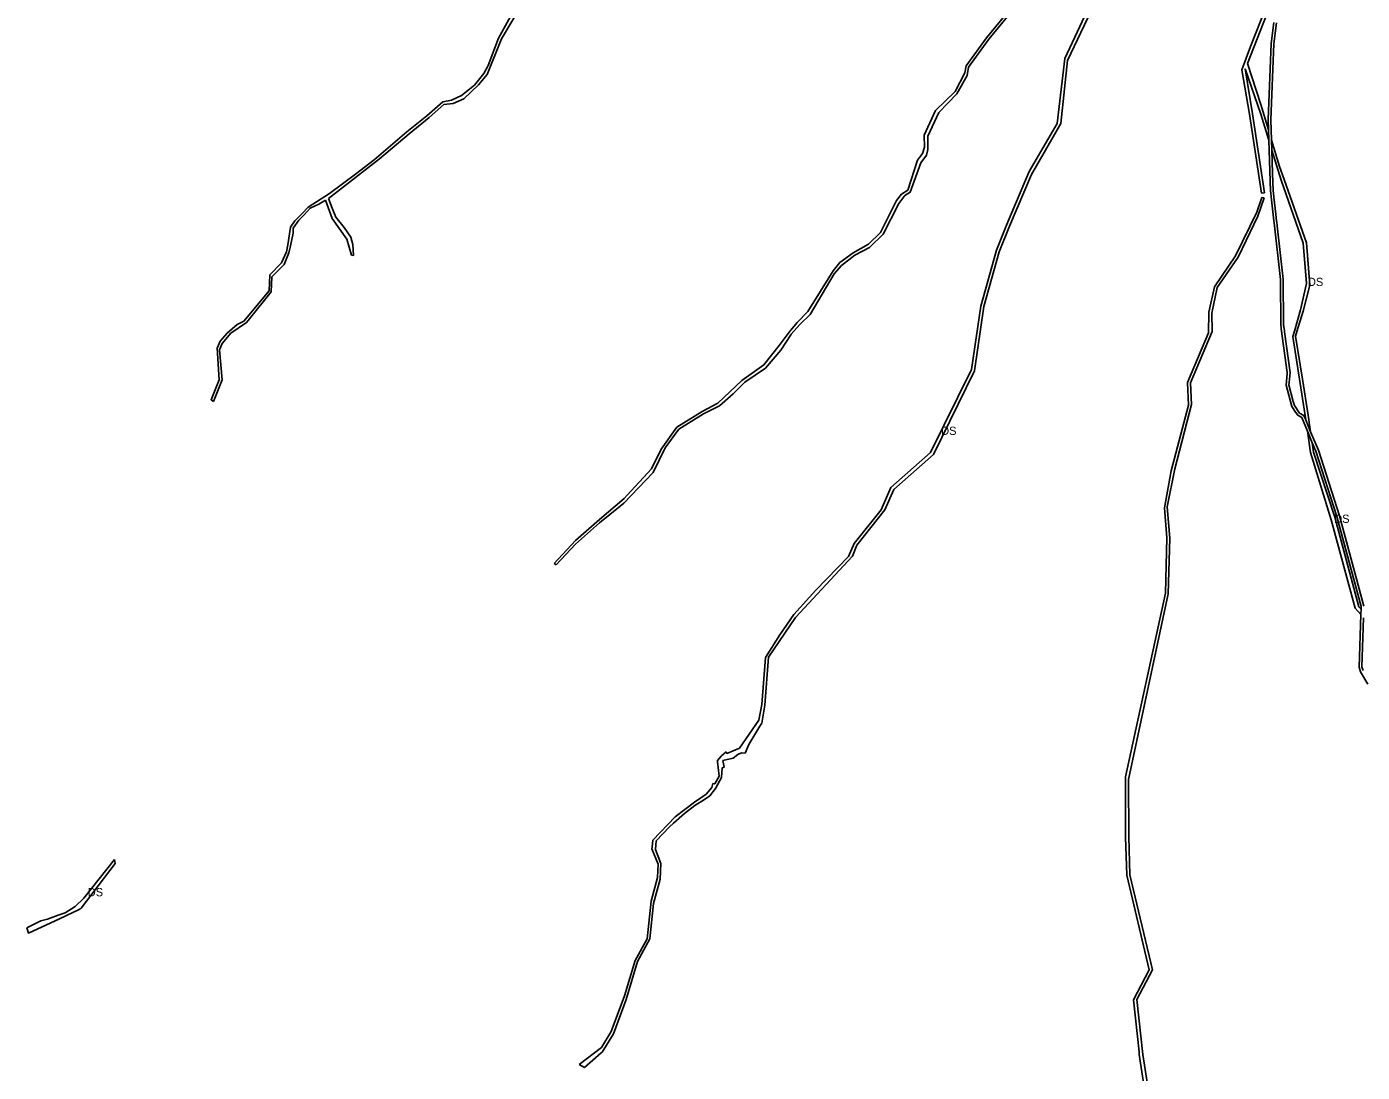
# Model space of a CAD drawing. Extents: x -477304 to -465641, y -1159113 to -1149285.
# Drawn here: x -475398 to -473942, y -1157333 to -1156193 of the extents above; entities that cross this region are included whole.
import ezdxf

# ---------------------------------------------------------------- set-up
doc = ezdxf.new("R2010")
doc.units = 0
doc.layers.add('35', color=7, linetype='Continuous')
doc.layers.add('4', color=7, linetype='Continuous')

msp = doc.modelspace()

# ---------------------------------------------------------------- linework, layer by layer
at = {"layer": '35'}
for p, q in [((-474263.1, -1156230.3), (-474209.5, -1156117.1)), ((-474861.1, -1156165.1), (-474883.8, -1156206)), ((-474045.7, -1156169.9), (-474063.4, -1156215)), ((-474883.8, -1156206), (-474894.9, -1156235.6)), ((-474052.4, -1156278.4), (-474066.8, -1156233.6)), ((-474069.5, -1156239.5), (-474052.4, -1156288.7)), ((-474933.1, -1156277.3), (-474921.4, -1156271.9)), ((-474961.9, -1156290.5), (-474983.6, -1156308.2)), ((-474044, -1156306), (-474052.4, -1156278.4)), ((-474052.4, -1156288.7), (-474043.6, -1156317.1)), ((-474043.6, -1156317.1), (-474044, -1156306)), ((-474983.6, -1156308.2), (-475019.2, -1156338.6)), ((-475013.4, -1156337.4), (-474981.2, -1156310.1)), ((-474419.6, -1156311.6), (-474419.2, -1156324.6)), ((-474031.9, -1156345.9), (-474040.6, -1156317.2)), ((-474040.6, -1156317.2), (-474040.2, -1156327.9)), ((-474040.2, -1156327.9), (-474030.1, -1156360.6)), ((-475069.1, -1156380.7), (-475013.4, -1156337.4)), ((-475019.2, -1156338.6), (-475039.6, -1156354.1)), ((-474026.8, -1156359.9), (-474031.9, -1156345.9)), ((-475039.6, -1156354.1), (-475068.2, -1156375.1)), ((-474305, -1156351.4), (-474329.7, -1156409.8)), ((-474326.2, -1156411), (-474302.2, -1156354.4)), ((-475068.2, -1156375.1), (-475091.4, -1156390.2)), ((-474051.6, -1156374.9), (-474048.3, -1156374.7)), ((-474048.7, -1156380), (-474051.2, -1156379.6)), ((-475079.7, -1156386.7), (-475072.4, -1156382.6)), ((-475072.4, -1156382.6), (-475065.2, -1156402.4)), ((-475065.1, -1156391.3), (-475069.1, -1156380.7)), ((-475061.2, -1156401), (-475065.1, -1156391.3)), ((-475105.9, -1156405.1), (-475110.5, -1156411.9)), ((-475052.1, -1156412.4), (-475061.2, -1156401)), ((-474329.7, -1156409.8), (-474340.5, -1156437.1)), ((-475041.8, -1156442.8), (-475042.4, -1156431)), ((-474495.1, -1156442.4), (-474479.2, -1156434.1)), ((-474340.5, -1156437.1), (-474357.5, -1156498.2)), ((-475131.1, -1156466.2), (-475117.6, -1156452.6)), ((-475044, -1156442.4), (-475041.8, -1156442.8)), ((-474496.7, -1156439.8), (-474511.4, -1156450.4)), ((-474079.8, -1156443.2), (-474102.7, -1156476.8)), ((-474099.7, -1156477.6), (-474077, -1156444.5)), ((-475133, -1156463.8), (-475134, -1156481.5)), ((-475131.5, -1156482.5), (-475131.1, -1156466.2)), ((-474543.6, -1156507.3), (-474517.5, -1156462.8)), ((-474105.8, -1156505.7), (-474099.7, -1156477.6)), ((-475155.1, -1156511.8), (-475131.5, -1156482.5)), ((-474554.9, -1156518.1), (-474543.6, -1156507.3)), ((-474012.9, -1156525.6), (-474006.2, -1156503.4)), ((-475158.5, -1156516), (-475155.1, -1156511.8)), ((-474565.6, -1156525), (-474577.7, -1156541)), ((-474014.3, -1156530.6), (-474012.9, -1156525.6)), ((-475190.6, -1156543.9), (-475188.5, -1156578.4)), ((-474592.6, -1156565.6), (-474575.7, -1156546)), ((-474409.3, -1156659.8), (-474364.4, -1156568.6)), ((-474003.3, -1156621.9), (-473997.9, -1156635)), ((-474689.1, -1156630.1), (-474706.4, -1156654.1)), ((-473996.1, -1156647), (-474001.4, -1156634.3)), ((-474001.4, -1156634.3), (-473997.9, -1156657.7)), ((-474706.4, -1156654.1), (-474716.9, -1156675.5)), ((-474714.9, -1156679.2), (-474701.9, -1156652.6)), ((-474452.4, -1156697.8), (-474409.3, -1156659.8)), ((-474799.8, -1156757.5), (-474773.7, -1156734.3)), ((-474820.7, -1156780.1), (-474799.8, -1156757.5)), ((-474822.9, -1156778.7), (-474820.7, -1156780.1)), ((-473942.9, -1156828.4), (-473945.3, -1156825.6)), ((-473943.1, -1156834.3), (-473942.9, -1156828.4)), ((-474596.6, -1156932.1), (-474599.7, -1156949.2)), ((-474596.5, -1156952.5), (-474593.1, -1156932.8)), ((-474610.7, -1156976), (-474598.6, -1156955.9)), ((-474598.6, -1156955.9), (-474596.5, -1156952.5)), ((-474614.7, -1156985.2), (-474610.7, -1156976)), ((-474639.2, -1156993.1), (-474627.9, -1156990.7)), ((-474627.9, -1156990.7), (-474622.6, -1156986.8)), ((-474622.6, -1156986.8), (-474618.7, -1156985)), ((-474618.7, -1156985), (-474614.7, -1156985.2)), ((-474644.7, -1156994.7), (-474644.2, -1157000.9)), ((-474644.2, -1157000.9), (-474642.9, -1157010.4)), ((-474640.6, -1157011.8), (-474639.9, -1157001.2)), ((-474639.9, -1157001.2), (-474637.5, -1157000.7)), ((-474637.5, -1157000.7), (-474639.2, -1156993.1)), ((-474650, -1157018.2), (-474651, -1157022.6)), ((-474647.1, -1157023.7), (-474640.6, -1157011.8)), ((-474660.9, -1157032.5), (-474670, -1157038.6)), ((-474669.4, -1157042.2), (-474659.2, -1157035.6)), ((-474657.3, -1157030.1), (-474660.9, -1157032.5)), ((-474659.2, -1157035.6), (-474653.1, -1157031.7)), ((-474651, -1157022.6), (-474657.3, -1157030.1)), ((-474653.1, -1157031.7), (-474647.1, -1157023.7)), ((-474716.1, -1157087.7), (-474716.3, -1157089.4)), ((-474712.3, -1157090.1), (-474711.8, -1157081)), ((-474706.6, -1157105.5), (-474712.3, -1157090.1)), ((-475339, -1157154.1), (-475301.8, -1157105.4)), ((-475301.8, -1157105.4), (-475302.4, -1157101.1)), ((-474718.6, -1157187.5), (-474714.6, -1157149.1)), ((-475341.1, -1157155.7), (-475339, -1157154.1)), ((-475382.7, -1157168.2), (-475398.3, -1157175.8)), ((-474732, -1157212.5), (-474718.6, -1157187.5)), ((-474187.4, -1157253.9), (-474170.3, -1157221.5)), ((-474181.1, -1157313.9), (-474187.4, -1157253.9)), ((-474790, -1157328), (-474771.6, -1157312)), ((-474771.6, -1157312), (-474770.6, -1157311.1)), ((-474185.1, -1157310.8), (-474184.8, -1157313.7)), ((-474795.9, -1157324.7), (-474790, -1157328)), ((-474184.8, -1157313.7), (-474179.7, -1157346.8)), ((-474175.7, -1157346.4), (-474181.1, -1157313.9))]:
    msp.add_line(p, q, dxfattribs=at)
for points in [[(-474204.1, -1156055.4), (-474206.1, -1156090.1), (-474206.5, -1156100.7), (-474266.2, -1156228.1)], [(-474372.4, -1156246.7), (-474371, -1156237.6), (-474349, -1156207.2), (-474328.4, -1156182.4), (-474319.5, -1156169.6), (-474292.1, -1156141.7), (-474279.6, -1156131)], [(-474066.8, -1156233.6), (-474042.5, -1156171.3), (-474049, -1156144.7)], [(-474921.4, -1156271.9), (-474905.6, -1156256.9), (-474896.2, -1156245.6), (-474880.6, -1156206.5), (-474861, -1156174.5)], [(-474331.2, -1156180.9), (-474351.5, -1156205.7), (-474373.5, -1156236.1)], [(-474063.4, -1156215), (-474073.1, -1156240.3), (-474064.5, -1156288.7), (-474051.6, -1156374.9)], [(-474266.2, -1156228.1), (-474274.3, -1156298.9), (-474305, -1156351.4)], [(-474302.2, -1156354.4), (-474270.3, -1156299.1), (-474263.1, -1156230.3)], [(-474894.9, -1156235.6), (-474899.6, -1156244.5), (-474909.7, -1156257)], [(-474373.5, -1156236.1), (-474375.2, -1156243.9), (-474385.7, -1156264.1), (-474407, -1156284.7), (-474419.6, -1156311.6)], [(-474403.5, -1156287.1), (-474383.8, -1156266.6), (-474372.4, -1156246.7)], [(-474048.3, -1156374.7), (-474061.3, -1156288.5), (-474069.5, -1156239.5)], [(-474909.7, -1156257), (-474923.9, -1156268.3), (-474935, -1156273.4)], [(-474981.2, -1156310.1), (-474959.5, -1156292.5), (-474943.3, -1156278.2), (-474933.1, -1156277.3)], [(-474935, -1156273.4), (-474944.5, -1156275.5), (-474961.9, -1156290.5)], [(-474415.5, -1156327.2), (-474415.5, -1156312.9), (-474403.5, -1156287.1)], [(-474447.2, -1156386.1), (-474440.4, -1156377.6), (-474434.7, -1156373.8), (-474423, -1156341.8), (-474416.8, -1156333.3), (-474415.5, -1156327.2)], [(-474419.2, -1156324.6), (-474421.3, -1156331.6), (-474426.7, -1156338.9), (-474437.3, -1156371.7)], [(-474030.1, -1156360.6), (-474006, -1156429.4), (-474002.3, -1156473.4), (-474008.9, -1156502), (-474015.5, -1156525.3)], [(-474006.2, -1156503.4), (-473998.8, -1156475.1), (-474002.6, -1156429), (-474026.8, -1156359.9)], [(-474437.3, -1156371.7), (-474444, -1156375.8), (-474449.6, -1156382.7), (-474467, -1156417.6)], [(-474051.2, -1156379.6), (-474056.6, -1156395.7), (-474079.8, -1156443.2)], [(-474077, -1156444.5), (-474055.5, -1156399.9), (-474048.7, -1156380)], [(-475091.4, -1156390.2), (-475097.7, -1156397), (-475105.9, -1156405.1)], [(-475099.5, -1156402.4), (-475095.6, -1156398.6), (-475089.1, -1156391.4), (-475079.7, -1156386.7)], [(-474479.2, -1156434.1), (-474464.3, -1156419.6), (-474447.2, -1156386.1)], [(-475110.7, -1156432.4), (-475107.5, -1156418.5), (-475107.7, -1156412.9), (-475101.6, -1156404.4), (-475099.5, -1156402.4)], [(-475065.2, -1156402.4), (-475049.1, -1156425.1), (-475044, -1156442.4)], [(-475110.5, -1156411.9), (-475113.4, -1156431.1), (-475115.1, -1156438.7), (-475120.4, -1156451), (-475133, -1156463.8)], [(-475042.4, -1156431), (-475044.8, -1156422.8), (-475052.1, -1156412.4)], [(-474467, -1156417.6), (-474480.3, -1156430.3), (-474496.7, -1156439.8)], [(-474364.4, -1156568.6), (-474354.5, -1156498.4), (-474337.5, -1156439), (-474326.2, -1156411)], [(-475117.6, -1156452.6), (-475112.4, -1156440.1), (-475110.7, -1156432.4)], [(-474511.4, -1156450.4), (-474518.7, -1156459.5), (-474546.2, -1156503.8)], [(-474517.5, -1156462.8), (-474509.7, -1156453.8), (-474495.1, -1156442.4)], [(-475134, -1156481.5), (-475161.3, -1156514.4), (-475168.6, -1156517.9), (-475179.8, -1156527.4), (-475187.2, -1156536.2), (-475190.6, -1156543.9)], [(-474102.7, -1156476.8), (-474108.8, -1156504.7), (-474109.3, -1156527.2), (-474132.2, -1156581.2), (-474131.2, -1156605.9), (-474149.9, -1156677.7)], [(-474357.5, -1156498.2), (-474367.9, -1156567), (-474412.4, -1156657.6), (-474455.7, -1156695.8), (-474466.3, -1156719.9), (-474495.8, -1156756.8), (-474502.1, -1156770.9), (-474537.5, -1156807.6), (-474561.7, -1156834.1), (-474576.9, -1156856.4)], [(-474546.2, -1156503.8), (-474558, -1156515.9), (-474565, -1156524.1), (-474565.6, -1156525)], [(-474129, -1156581.5), (-474105.4, -1156525.8), (-474105.8, -1156505.7)], [(-475188, -1156545.7), (-475185.2, -1156538.7), (-475175.8, -1156527.6), (-475158.5, -1156516)], [(-474575.7, -1156546), (-474564.9, -1156529.3), (-474564.4, -1156528.4), (-474554.9, -1156518.1)], [(-474015.5, -1156525.3), (-474017.2, -1156531), (-474003.3, -1156621.9)], [(-473997.9, -1156635), (-474000.5, -1156616.7), (-474006.9, -1156577.7), (-474014.3, -1156530.6)], [(-475194.6, -1156602.1), (-475185.2, -1156578.4), (-475188, -1156545.7)], [(-474577.7, -1156541), (-474594.2, -1156562.1), (-474618.4, -1156578.9), (-474644.6, -1156603.6), (-474661.6, -1156612.8), (-474689.1, -1156630.1)], [(-474660.2, -1156615.4), (-474642.8, -1156606.7), (-474627.9, -1156593.6), (-474615.1, -1156580.8), (-474592.6, -1156565.6)], [(-475188.5, -1156578.4), (-475197.2, -1156600.1), (-475194.6, -1156602.1)], [(-474170.3, -1157221.5), (-474195, -1157118), (-474196.3, -1157076.5), (-474196.7, -1157013.8), (-474153.3, -1156811.7), (-474151.4, -1156751), (-474154.4, -1156716.7), (-474145.9, -1156675.2), (-474127.9, -1156605.1), (-474129, -1156581.5)], [(-474701.9, -1156652.6), (-474686.9, -1156632.3), (-474660.2, -1156615.4)], [(-473945.3, -1156825.6), (-473971.7, -1156728.1), (-473994.7, -1156657.1), (-473996.1, -1156647)], [(-473997.9, -1156657.7), (-473975.4, -1156730.9), (-473949.5, -1156827.2), (-473943.1, -1156834.3)], [(-474773.7, -1156734.3), (-474751.1, -1156716.1), (-474747, -1156712.7), (-474714.9, -1156679.2)], [(-474716.9, -1156675.5), (-474743.4, -1156704.1), (-474746.7, -1156707.7), (-474773.6, -1156730.6)], [(-474149.9, -1156677.7), (-474157.5, -1156717.9), (-474154.6, -1156750.7), (-474156.4, -1156810.7)], [(-474559.7, -1156837.5), (-474497.6, -1156770.5), (-474492.7, -1156758.4), (-474462.3, -1156720.2), (-474452.4, -1156697.8)], [(-474773.6, -1156730.6), (-474799.8, -1156753.5), (-474822.9, -1156778.7)], [(-474156.4, -1156810.7), (-474199.7, -1157011.2), (-474199.9, -1157076.7), (-474198.4, -1157118.1), (-474174, -1157221.4)], [(-474593.1, -1156932.8), (-474589.3, -1156880.5), (-474559.7, -1156837.5)], [(-474576.9, -1156856.4), (-474592.6, -1156881), (-474596.6, -1156932.1)], [(-474599.7, -1156949.2), (-474620.9, -1156979.8), (-474634.6, -1156985.6), (-474635.3, -1156983.8)], [(-474635.3, -1156983.8), (-474640.4, -1156988.3), (-474644.8, -1156993.2), (-474644.7, -1156994.7)], [(-474642.9, -1157010.4), (-474647.8, -1157018.8), (-474650, -1157018.2)], [(-474670, -1157038.6), (-474691.1, -1157054.6), (-474715.2, -1157080.2), (-474716.1, -1157087.7)], [(-474693, -1157061.4), (-474680.7, -1157050.9), (-474669.4, -1157042.2)], [(-474711.8, -1157081), (-474697.1, -1157065.7), (-474693, -1157061.4)], [(-474716.3, -1157089.4), (-474709.5, -1157106.2), (-474710.2, -1157120.9), (-474717.1, -1157146.5)], [(-475302.4, -1157101.1), (-475336, -1157143.5), (-475345.3, -1157152.4), (-475356.5, -1157159.3), (-475364, -1157161.9), (-475375.7, -1157166.1), (-475382.7, -1157168.2)], [(-474714.6, -1157149.1), (-474707.5, -1157122.5), (-474706.6, -1157105.5)], [(-474717.1, -1157146.5), (-474721.5, -1157187.6), (-474734.8, -1157211.4)], [(-475398.3, -1157175.8), (-475396.4, -1157181.4), (-475362.5, -1157165.8), (-475341.1, -1157155.7)], [(-474770.6, -1157311.1), (-474758.3, -1157291.3), (-474744.5, -1157253.7), (-474732, -1157212.5)], [(-474734.8, -1157211.4), (-474746.2, -1157249.8), (-474759.6, -1157285.6)], [(-474174, -1157221.4), (-474191.1, -1157254), (-474185.1, -1157310.8)], [(-474759.6, -1157285.6), (-474760.7, -1157288.6), (-474771.5, -1157306), (-474795.9, -1157324.7)]]:
    msp.add_lwpolyline(points, dxfattribs=at)
at = {"layer": '4'}
for points in [[(-474038, -1156188.9), (-474041.1, -1156211.9), (-474044.4, -1156294.7), (-474044, -1156306), (-474043.6, -1156317.1), (-474041.7, -1156372.6), (-474041.5, -1156374.4), (-474041, -1156378.9), (-474038.1, -1156405), (-474037.8, -1156407.1), (-474030.8, -1156469), (-474030.4, -1156519.3), (-474030.1, -1156521.2), (-474029.9, -1156522.8), (-474023.4, -1156570.3), (-474023.5, -1156571.4), (-474024.6, -1156584.2), (-474018.5, -1156607.5), (-474014.3, -1156613.5), (-474012, -1156616.9), (-474007.6, -1156619.3), (-474001.4, -1156634.3), (-473996.1, -1156647), (-473992.3, -1156656.2), (-473969.3, -1156727.3), (-473942.8, -1156825.3), (-473942.9, -1156828.4), (-473943.1, -1156834.3), (-473945.1, -1156891.4), (-473943.4, -1156896.5), (-473935.5, -1156910.2)], [(-473939.8, -1156825), (-473966.5, -1156726.5), (-473989.5, -1156655.1), (-473997.9, -1156635), (-474003.3, -1156621.9), (-474005.3, -1156617.2), (-474009.9, -1156614.6), (-474015.7, -1156606.3), (-474016.9, -1156601.8), (-474021.6, -1156583.9), (-474021.4, -1156581.3), (-474020.4, -1156570.2), (-474026.4, -1156526.1), (-474026.6, -1156525.1), (-474027.2, -1156520.2), (-474027.4, -1156519.1), (-474027.4, -1156517.6), (-474027.8, -1156468.8), (-474034.4, -1156410.6), (-474034.9, -1156406.2), (-474035, -1156405.3), (-474035.8, -1156397.9), (-474038, -1156379.2), (-474038.5, -1156374.8), (-474038.7, -1156372.4), (-474039.4, -1156353), (-474040.2, -1156327.9), (-474040.6, -1156317.2), (-474041.4, -1156294.8), (-474038.1, -1156212.2), (-474035, -1156189.3)], [(-473940.7, -1156895.2), (-473942.1, -1156891), (-473940.3, -1156837.6)]]:
    msp.add_lwpolyline(points, dxfattribs=at)

# ---------------------------------------------------------------- texts
at = {"layer": '35'}
for p in [(-474000.9, -1156476.1), (-474400.9, -1156638.4), (-473972.2, -1156734.3), (-475331.7, -1157141.3)]:
    msp.add_text('DS', height=9, dxfattribs=at).set_placement(p)

doc.saveas('drawing.dxf')
